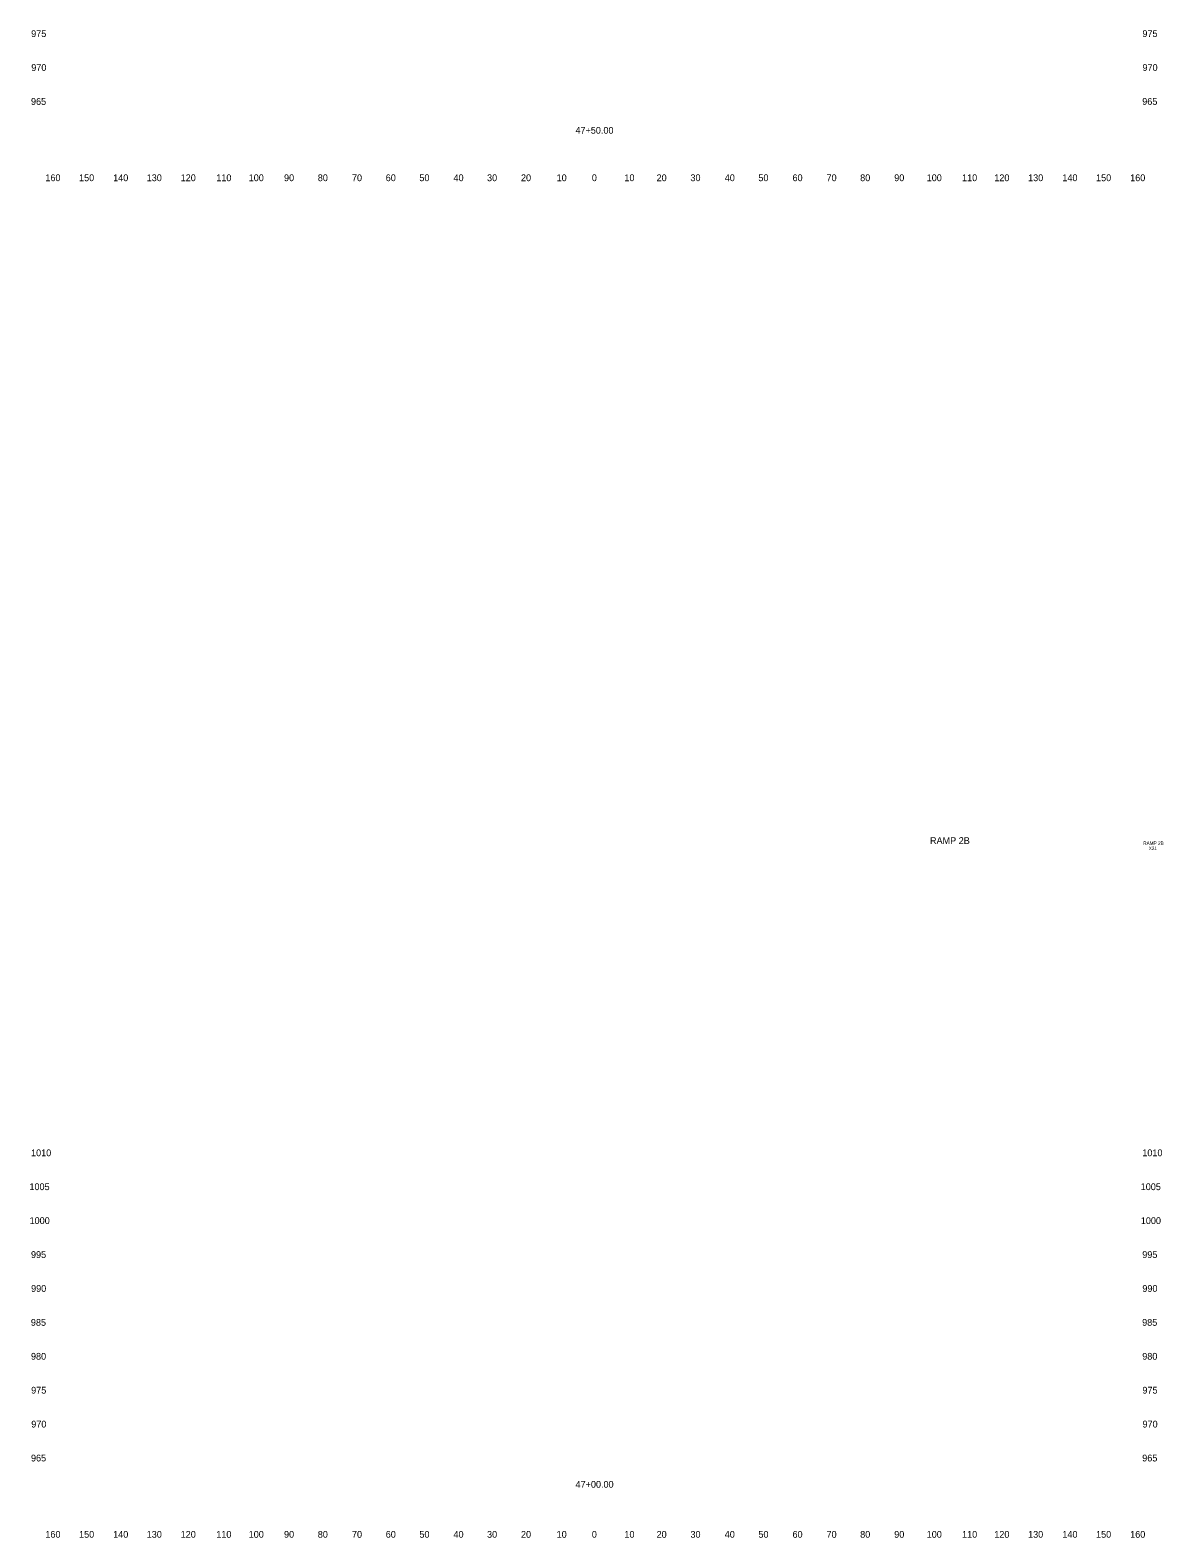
# Model space of a CAD drawing. Extents: x 4994 to 6358, y 4997 to 8804.
# Drawn here: x 6023.6 to 6357.7, y 4997.5 to 5442 of the extents above; entities that cross this region are included whole.
import ezdxf

# ---------------------------------------------------------------- set-up
doc = ezdxf.new("R2010")
doc.units = 0
for name, color, linetype in [('RD_SHT_ID', 7, 'Continuous'), ('RD_XS_TX_Offset', 7, 'Continuous'), ('RD_XS_TX_Station', 7, 'Continuous')]:
    doc.layers.add(name, color=color, linetype=linetype)

msp = doc.modelspace()

# ---------------------------------------------------------------- texts
at = {"layer": 'RD_SHT_ID'}
for s, height, p in [('RAMP 2B', 2, (6289.05, 5202.06)), ('RAMP 2B', 1, (6351.94, 5201.8)), ('X21', 1, (6353.57, 5200.3))]:
    msp.add_text(s, height=height, dxfattribs=at).set_placement(p)
at = {"layer": 'RD_XS_TX_Offset'}
for s, p in [('975', (6023.91, 5440)), ('975', (6351.71, 5440)), ('970', (6023.94, 5430)), ('970', (6351.74, 5430)), ('965', (6023.86, 5420)), ('965', (6351.66, 5420)), ('160', (6028.1, 5397.5)), ('150', (6038.04, 5397.5)), ('140', (6048.1, 5397.5)), ('130', (6057.99, 5397.5)), ('120', (6068.01, 5397.5)), ('110', (6078.51, 5397.5)), ('100', (6088.07, 5397.5)), ('90', (6098.5, 5397.5)), ('80', (6108.46, 5397.5)), ('70', (6118.54, 5397.5)), ('60', (6128.5, 5397.5)), ('50', (6138.43, 5397.5)), ('40', (6148.5, 5397.5)), ('30', (6158.39, 5397.5)), ('20', (6168.4, 5397.5)), ('10', (6178.91, 5397.5)), ('0', (6189.3, 5397.5)), ('0', (6189.3, 5397.5)), ('10', (6198.91, 5397.5)), ('20', (6208.4, 5397.5)), ('30', (6218.39, 5397.5)), ('40', (6228.5, 5397.5)), ('50', (6238.43, 5397.5)), ('60', (6248.5, 5397.5)), ('70', (6258.54, 5397.5)), ('80', (6268.46, 5397.5)), ('90', (6278.5, 5397.5)), ('100', (6288.07, 5397.5)), ('110', (6298.51, 5397.5)), ('120', (6308.01, 5397.5)), ('130', (6317.99, 5397.5)), ('140', (6328.1, 5397.5)), ('150', (6338.04, 5397.5)), ('160', (6348.1, 5397.5)), ('1010', (6023.88, 5110)), ('1010', (6351.68, 5110)), ('1005', (6023.4, 5100)), ('1005', (6351.2, 5100)), ('1000', (6023.44, 5090)), ('1000', (6351.24, 5090)), ('995', (6023.86, 5080)), ('995', (6351.66, 5080)), ('990', (6023.89, 5070)), ('990', (6351.69, 5070)), ('985', (6023.83, 5060)), ('985', (6351.63, 5060)), ('980', (6023.86, 5050)), ('980', (6351.66, 5050)), ('975', (6023.91, 5040)), ('975', (6351.71, 5040)), ('970', (6023.94, 5030)), ('970', (6351.74, 5030)), ('965', (6023.86, 5020)), ('965', (6351.66, 5020)), ('160', (6028.1, 4997.5)), ('150', (6038.04, 4997.5)), ('140', (6048.1, 4997.5)), ('130', (6057.99, 4997.5)), ('120', (6068.01, 4997.5)), ('110', (6078.51, 4997.5)), ('100', (6088.07, 4997.5)), ('90', (6098.5, 4997.5)), ('80', (6108.46, 4997.5)), ('70', (6118.54, 4997.5)), ('60', (6128.5, 4997.5)), ('50', (6138.43, 4997.5)), ('40', (6148.5, 4997.5)), ('30', (6158.39, 4997.5)), ('20', (6168.4, 4997.5)), ('10', (6178.91, 4997.5)), ('0', (6189.3, 4997.5)), ('0', (6189.3, 4997.5)), ('10', (6198.91, 4997.5)), ('20', (6208.4, 4997.5)), ('30', (6218.39, 4997.5)), ('40', (6228.5, 4997.5)), ('50', (6238.43, 4997.5)), ('60', (6248.5, 4997.5)), ('70', (6258.54, 4997.5)), ('80', (6268.46, 4997.5)), ('90', (6278.5, 4997.5)), ('100', (6288.07, 4997.5)), ('110', (6298.51, 4997.5)), ('120', (6308.01, 4997.5)), ('130', (6317.99, 4997.5)), ('140', (6328.1, 4997.5)), ('150', (6338.04, 4997.5)), ('160', (6348.1, 4997.5))]:
    msp.add_text(s, height=2, dxfattribs=at).set_placement(p)
at = {"layer": 'RD_XS_TX_Station'}
for s, p in [('47+50.00', (6184.46, 5411.5)), ('47+00.00', (6184.5, 5012.25))]:
    msp.add_text(s, height=2, dxfattribs=at).set_placement(p)

doc.saveas('drawing.dxf')
